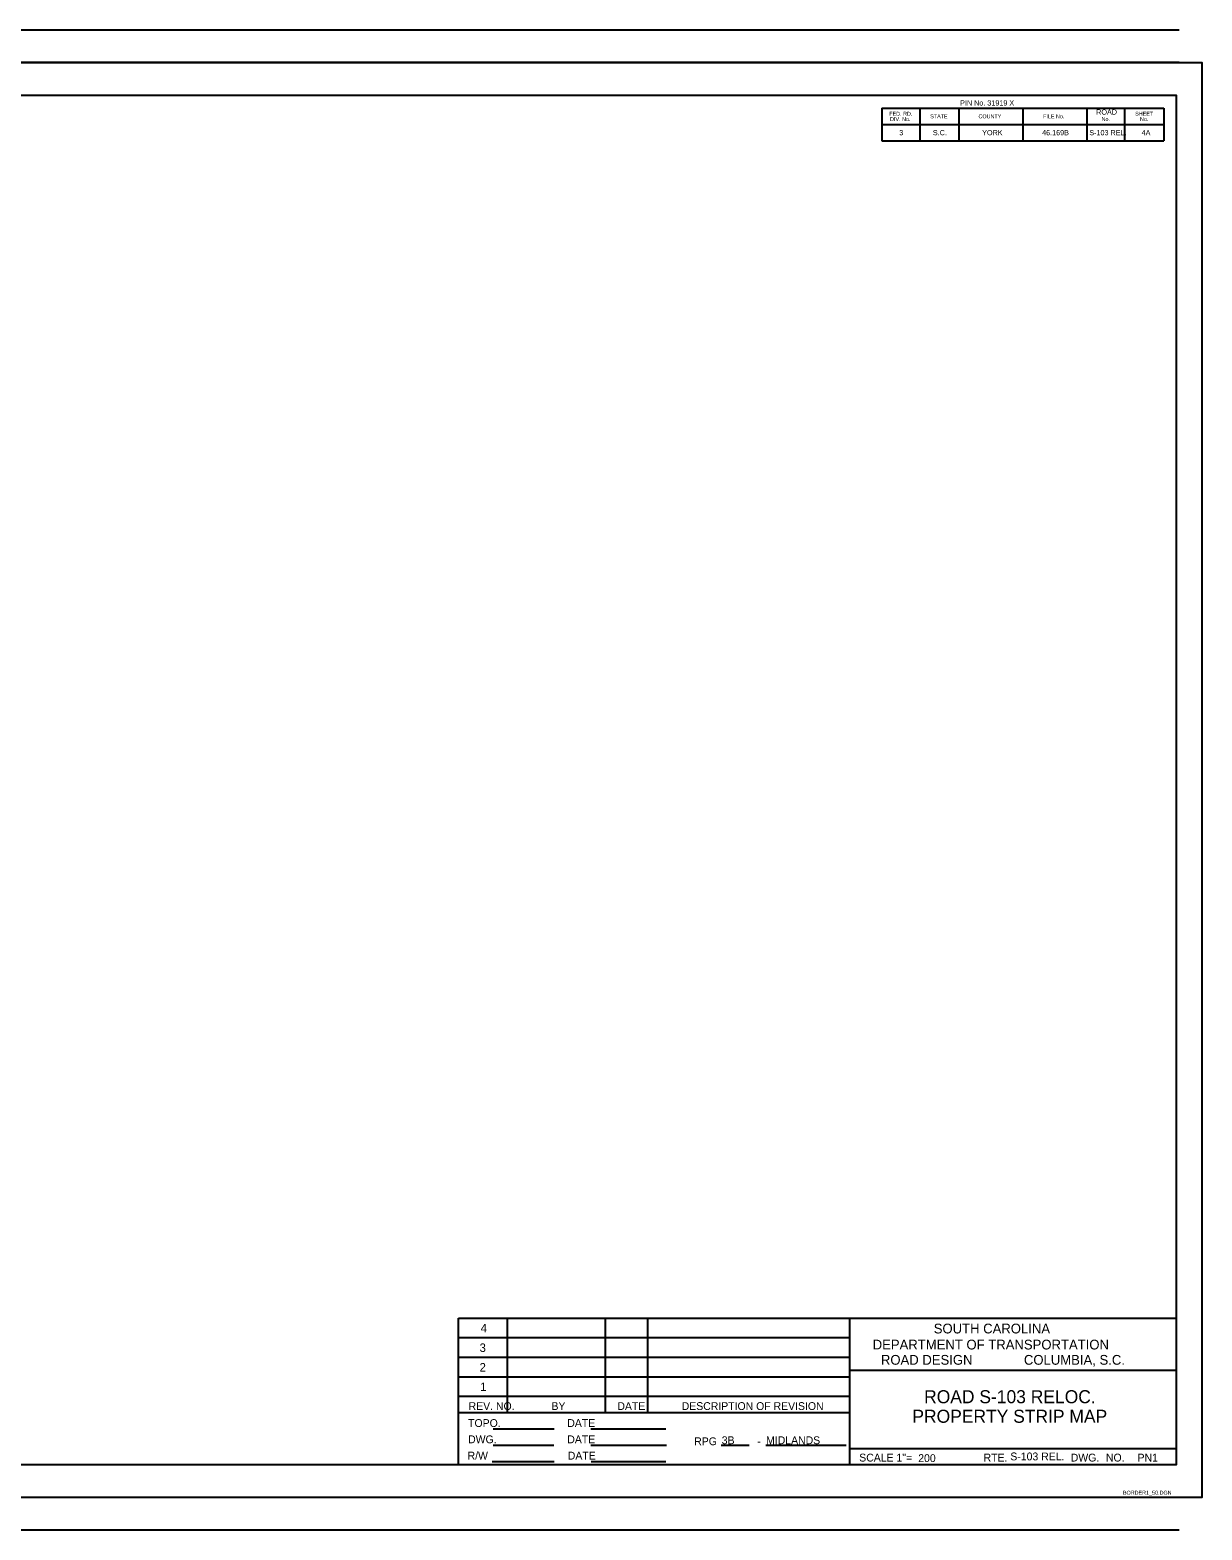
# Model space of a CAD drawing. Extents: x -189 to 1607, y -50 to 1100.
# Drawn here: x 709 to 1607, y -50 to 1100 of the extents above; entities that cross this region are included whole.
import ezdxf

# ---------------------------------------------------------------- set-up
doc = ezdxf.new("R2010")
doc.units = 0
for name, color, linetype in [('RD_SHT_Bndy', 7, 'Continuous'), ('RD_SHT_IplotShp', 7, 'Continuous'), ('RD_SHT_TX', 7, 'Continuous')]:
    doc.layers.add(name, color=color, linetype=linetype)

msp = doc.modelspace()

# ---------------------------------------------------------------- linework, layer by layer
at = {"layer": 'RD_SHT_Bndy'}
for p, q in [((1589.9, 1100), (-170.1, 1100)), ((1589.9, 1075), (-170.1, 1075)), ((1362, 1040), (1362, 1015)), ((1362, 1040), (1519, 1040)), ((1391, 1040), (1391, 1015)), ((1421, 1040), (1421, 1015)), ((1470, 1040), (1470, 1015)), ((1519, 1040), (1519, 1015)), ((1519, 1040), (1578, 1040)), ((1548, 1040), (1548, 1015)), ((1578, 1040), (1578, 1015)), ((1362, 1027.5), (1519, 1027.5)), ((1519, 1027.5), (1578, 1027.5)), ((1362, 1015), (1519, 1015)), ((1519, 1015), (1578, 1015)), ((1037.5, 0), (1037.5, 112.5)), ((1037.5, 112.5), (1587.5, 112.5)), ((1075, 39.9), (1075, 112.5)), ((1150, 39.9), (1150, 112.5)), ((1182.5, 39.9), (1182.5, 112.5)), ((1337.5, 0), (1337.5, 112.5)), ((1037.5, 97.5), (1337.5, 97.5)), ((1037.5, 82.5), (1337.5, 82.5)), ((1337.5, 72.5), (1587.5, 72.5)), ((1037.5, 67.5), (1337.5, 67.5)), ((1037.5, 52.5), (1337.5, 52.5)), ((1037.5, 40), (1337.5, 40)), ((1064, 27.5), (1110.8, 27.5)), ((1138.8, 27.5), (1196.4, 27.5)), ((1064, 15), (1110.4, 15)), ((1138.8, 15), (1196.8, 15)), ((1238.7, 15), (1260.1, 15)), ((1273, 15), (1334.6, 15)), ((1337.5, 12.5), (1587.5, 12.5)), ((1063.2, 2.5), (1110.8, 2.5)), ((1139.2, 2.5), (1196.4, 2.5)), ((1589.9, -25), (-170.1, -25)), ((1589.9, -50), (-170.1, -50))]:
    msp.add_line(p, q, dxfattribs=at)
msp.add_lwpolyline([(-87.5, 1050), (1587.5, 1050), (1587.5, 0), (-87.5, 0)], close=True, dxfattribs=at)
at = {"layer": 'RD_SHT_IplotShp'}
msp.add_lwpolyline([(-188.7, 1075), (1607.3, 1075), (1607.3, -25), (-188.7, -25)], close=True, dxfattribs=at)

# ---------------------------------------------------------------- texts
at = {"layer": 'RD_SHT_TX'}
for s, height, p in [('FED. RD.', 3, (1367.6, 1034.3)), ('STATE', 3, (1399, 1032.3)), ('PIN No. 31919 X   ', 4, (1421.9, 1042.1)), ('COUNTY', 3, (1436, 1032.3)), ('FILE No.', 3, (1485.5, 1032.3)), ('      ROAD      ', 4, (1517, 1035.1)), ('SHEET', 3, (1556.1, 1034.3)), ('DIV. No.', 3, (1368.2, 1030.2)), ('No.', 3, (1530.3, 1030.2)), ('No.', 3, (1559.8, 1030.2)), ('3', 4, (1375.3, 1019.3)), ('S.C.', 4, (1401, 1019.3)), ('      YORK      ', 4, (1429.6, 1019.3)), ('    46.169B    ', 4, (1478.6, 1019.3)), ('   S-103 REL.   ', 4, (1516.3, 1019.3)), ('       4A       ', 4, (1550.3, 1019.3)), ('4', 6.5, (1054.4, 101.5)), ('SOUTH CAROLINA', 7.5, (1401.7, 100.7)), ('3', 6.5, (1053.6, 86.5)), ('DEPARTMENT OF TRANSPORTATION', 7.5, (1354.9, 88.4)), ('ROAD DESIGN', 7.5, (1361.2, 76.7)), ('COLUMBIA, S.C.', 7.5, (1470.8, 76.7)), ('2', 6.5, (1053.6, 71.5)), ('1', 6.5, (1054, 56.5)), ('REV. NO.', 6, (1045.2, 42)), ('BY', 6, (1108.7, 42)), ('DATE', 6, (1159.2, 42)), ('DESCRIPTION OF REVISION', 6, (1208.5, 42)), ('ROAD S-103 RELOC.', 10, (1394.3, 47.2)), ('TOPO.', 6, (1044.8, 29)), ('DATE', 6, (1120.8, 29)), ('PROPERTY STRIP MAP', 10, (1385.3, 32.2)), ('DWG.', 6, (1044.8, 16.5)), ('DATE', 6, (1120.8, 16.5)), ('RPG', 6, (1218.1, 15)), ('3B    ', 6, (1239.2, 15.8)), ('-', 6, (1266.4, 15)), ('MIDLANDS  ', 6, (1273.2, 15.8)), ('R/W', 6, (1044.4, 4)), ('DATE', 6, (1121.2, 4)), ('SCALE 1"=', 6, (1344.6, 2.5)), ('200  ', 6, (1389.8, 2.1)), ('RTE.', 6, (1439.9, 2.5)), ('S-103 REL. ', 6, (1460.4, 3.4)), ('DWG.', 6, (1506.7, 2.5)), ('NO.', 6, (1533.7, 2.5)), ('PN1', 6, (1557.9, 2.5)), ('BORDER1_50.DGN', 3, (1546.7, -22.9))]:
    msp.add_text(s, height=height, dxfattribs=at).set_placement(p)

doc.saveas('drawing.dxf')
